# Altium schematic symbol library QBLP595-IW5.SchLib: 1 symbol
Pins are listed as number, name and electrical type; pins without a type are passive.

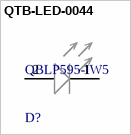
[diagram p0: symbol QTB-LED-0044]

## QTB-LED-0044
designator D?, comment QBLP595-IW5
LED WHITE DIFFUSED 0402 SMD; Manufacturer: QT Brightek (QTB); Luminous Intensity: 55mcd; Viewing Angle: 150°; Forward Voltage: 2.9V; Test Current: 5mA; Lens Style: Flat; Lens Size: 0.5mm
footprint FP-QBLP595-IW5-MFG
pins: 1 CATHODE (-), 2 ANODE (+)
